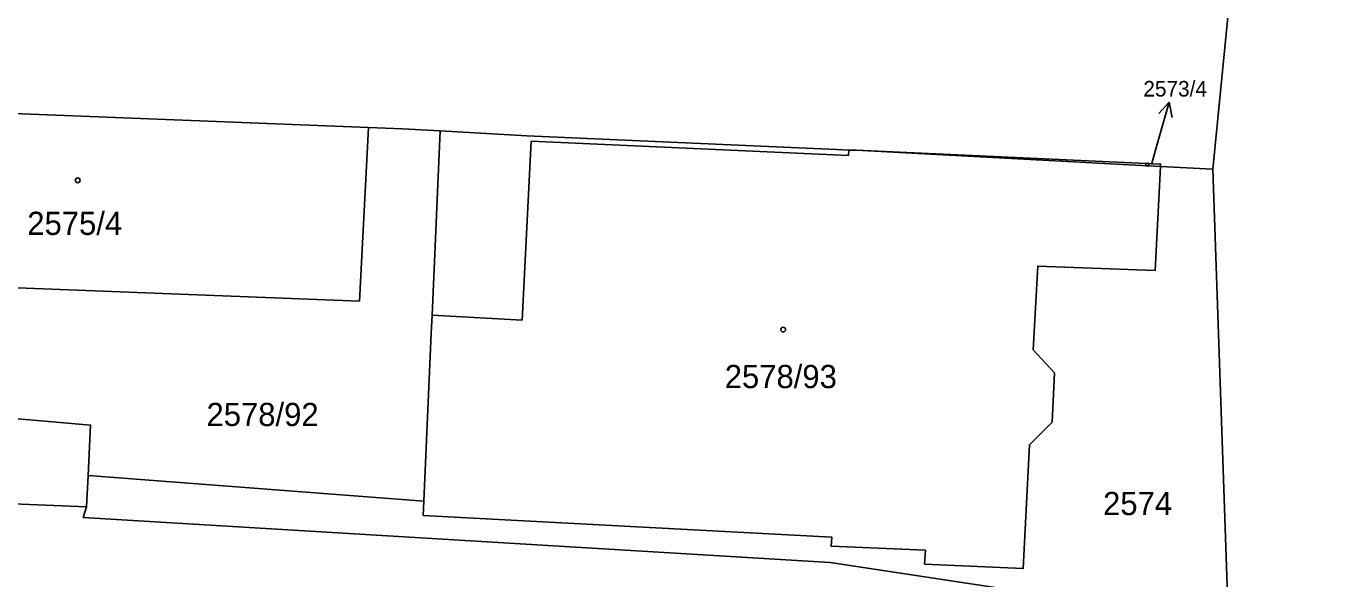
# Model space of a CAD drawing. Extents: x -527335 to -526256, y -1079142 to -1077809.
# Drawn here: x -526700.3 to -526603.8, y -1078291.1 to -1078250.6 of the extents above; entities that cross this region are included whole.
import ezdxf

# ---------------------------------------------------------------- set-up
doc = ezdxf.new("R2010")
doc.units = 0
for name, color, linetype in [('Vrstva 1', 7, 'Continuous'), ('Vrstva 2', 7, 'Continuous'), ('Vrstva 4', 7, 'Continuous'), ('Vrstva 5', 7, 'Continuous'), ('Vrstva 7', 7, 'Continuous')]:
    doc.layers.add(name, color=color, linetype=linetype)

msp = doc.modelspace()

# ---------------------------------------------------------------- linework, layer by layer
at = {"layer": 'Vrstva 1'}
for p, q in [((-526603.75, -1078162.52), (-526613.4, -1078261.09)), ((-526717.88, -1078256.37), (-526675.26, -1078258.03)), ((-526617.25, -1078260.89), (-526639.54, -1078259.71)), ((-526617.25, -1078260.89), (-526613.4, -1078261.09)), ((-526613.4, -1078261.09), (-526612.35, -1078291.6)), ((-526695.81, -1078283.53), (-526695.92, -1078285.82)), ((-526671.21, -1078285.41), (-526695.81, -1078283.53)), ((-526719.79, -1078284.89), (-526695.92, -1078285.82))]:
    msp.add_line(p, q, dxfattribs=at)
for points in [[(-526718.54, -1078268.81), (-526718.55, -1078269.1), (-526675.94, -1078270.75), (-526675.26, -1078258.03)], [(-526675.26, -1078258.03), (-526672.79, -1078258.13), (-526670.02, -1078258.29)], [(-526671.21, -1078285.41), (-526670.67, -1078273.12), (-526670.61, -1078271.78), (-526670.02, -1078258.29)], [(-526670.02, -1078258.29), (-526663.67, -1078258.65), (-526640.99, -1078259.65), (-526640.08, -1078259.69), (-526639.54, -1078259.71)], [(-526639.54, -1078259.71), (-526617.24, -1078260.72), (-526617.25, -1078260.89)], [(-526617.25, -1078260.89), (-526617.62, -1078268.51), (-526626.24, -1078268.19), (-526626.56, -1078274.33), (-526625.01, -1078276.02), (-526625.18, -1078279.62), (-526626.84, -1078281.28), (-526627.3, -1078290.35), (-526634.53, -1078290.02), (-526634.47, -1078289), (-526641.38, -1078288.71), (-526641.33, -1078288.04), (-526671.26, -1078286.45), (-526671.21, -1078285.41)], [(-526719.23, -1078270.66), (-526708.29, -1078271.04), (-526708.33, -1078271.55), (-526708.81, -1078278.7), (-526695.63, -1078279.84), (-526695.81, -1078283.53)], [(-526695.92, -1078285.82), (-526696.17, -1078286.6), (-526641.44, -1078289.9), (-526627.42, -1078292.02), (-526614.86, -1078298.09), (-526612.81, -1078296.77), (-526612.35, -1078291.6)]]:
    msp.add_lwpolyline(points, dxfattribs=at)
at = {"layer": 'Vrstva 4'}
for p, q in [((-526663.35, -1078259.03), (-526664, -1078272.15)), ((-526640.1, -1078260.09), (-526663.35, -1078259.03)), ((-526640.08, -1078259.69), (-526640.1, -1078260.09)), ((-526664, -1078272.15), (-526670.61, -1078271.78))]:
    msp.add_line(p, q, dxfattribs=at)
at = {"layer": 'Vrstva 5'}
for centre, radius in [((-526618.205, -1078260.759), 0.117), ((-526696.577, -1078261.909), 0.175), ((-526644.887, -1078272.839), 0.175)]:
    msp.add_circle(centre, radius, dxfattribs=at)
at = {"layer": 'Vrstva 7'}
for p, q in [((-526617.43, -1078259.08), (-526616.603, -1078256.195)), ((-526616.603, -1078256.195), (-526617.36, -1078257.02)), ((-526616.603, -1078256.195), (-526616.398, -1078257.296)), ((-526617.9, -1078260.75), (-526617.43, -1078259.08))]:
    msp.add_line(p, q, dxfattribs=at)

# ---------------------------------------------------------------- texts
at = {"layer": 'Vrstva 2'}
for s, height, p in [('2573/4', 1.14, (-526618.5, -1078255.77)), ('2575/4', 1.7, (-526700.27, -1078265.91)), ('2578/93', 1.7, (-526649.17, -1078277.13)), ('2578/92', 1.7, (-526687.14, -1078279.91)), ('2574', 1.7, (-526621.449, -1078286.43))]:
    msp.add_text(s, height=height, dxfattribs=at).set_placement(p)

doc.saveas('drawing.dxf')
